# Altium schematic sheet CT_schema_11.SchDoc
size 297 x 239 mm
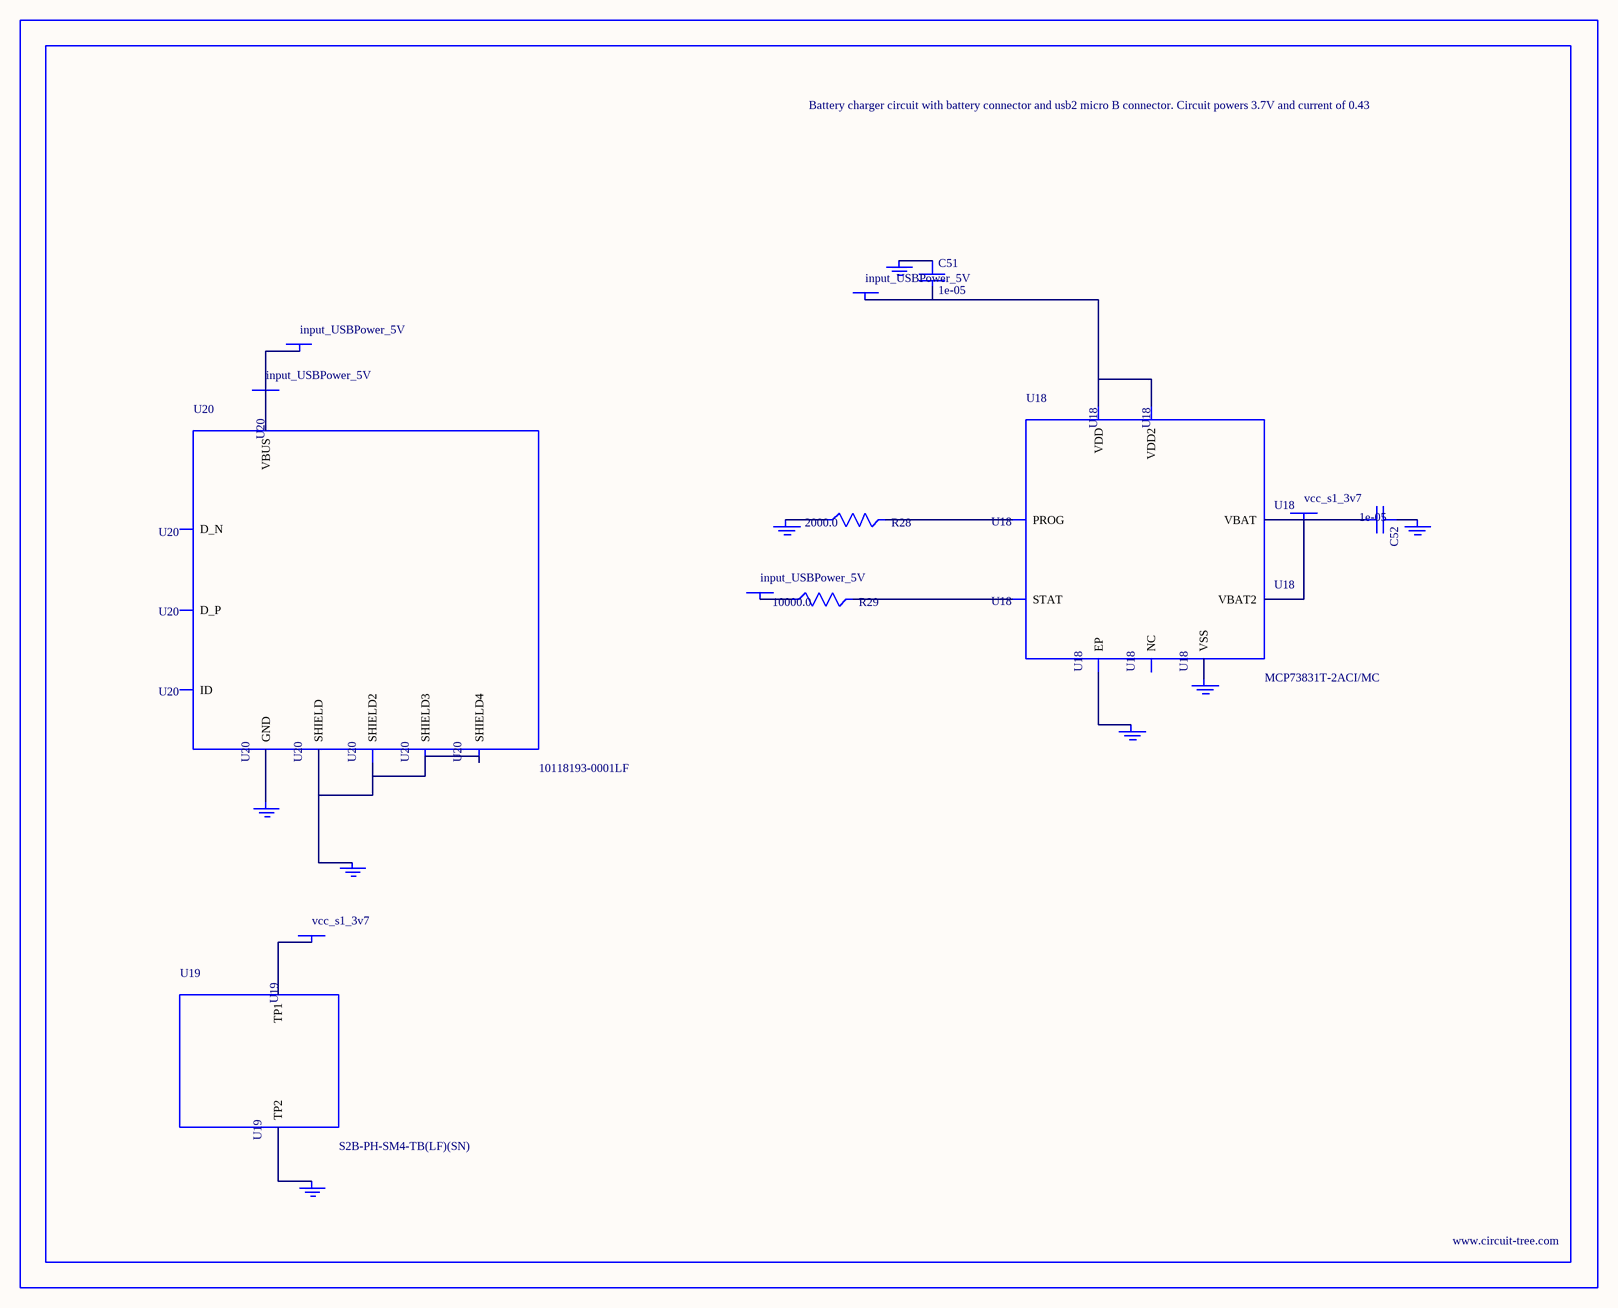
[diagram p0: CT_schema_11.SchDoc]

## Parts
BORDER10  (no value)
C51  1e-05  [C1206]
C52  1e-05  [C1206]
GND_INSTANCE_10_0  (no value)
GND_INSTANCE_10_1  (no value)
GND_INSTANCE_10_2  (no value)
GND_INSTANCE_10_3  (no value)
GND_INSTANCE_10_4  (no value)
GND_INSTANCE_10_5  (no value)
GND_INSTANCE_10_6  (no value)
GND_INSTANCE_10_7  (no value)
POWER_INSTANCE_10_0  input_USBPower_5V
POWER_INSTANCE_10_1  input_USBPower_5V
POWER_INSTANCE_10_2  vcc_s1_3v7
POWER_INSTANCE_10_3  vcc_s1_3v7
POWER_INSTANCE_10_4  input_USBPower_5V
POWER_INSTANCE_10_5  input_USBPower_5V
R28  2000.0  [R0603]
R29  10000.0  [R0603]
U18  MCP73831T-2ACI/MC  [DFN8_2X3MC]
U19  S2B-PH-SM4-TB(LF)(SN)  [JST-2-SMD]
U20  10118193-0001LF  [FCI_10118193-0001LF]

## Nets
NetC51_1: C51.1 GND_INSTANCE_10_0.0(GND)
NetC51_2: C51.2 POWER_INSTANCE_10_0.0(PWR) U18.1(VDD) U18.2(VDD2)
NetC52_1: C52.1 GND_INSTANCE_10_1.0(GND)
NetC52_2: C52.2 POWER_INSTANCE_10_2.0(PWR) U18.3(VBAT) U18.4(VBAT2)
NetGND_INSTANCE_10_2_0: GND_INSTANCE_10_2.0(GND) R28.1
NetGND_INSTANCE_10_3_0: GND_INSTANCE_10_3.0(GND) U18.9(EP)
NetGND_INSTANCE_10_4_0: GND_INSTANCE_10_4.0(GND) U18.6(VSS)
NetGND_INSTANCE_10_5_0: GND_INSTANCE_10_5.0(GND) U19.2(TP2)
NetGND_INSTANCE_10_6_0: GND_INSTANCE_10_6.0(GND) U20.6(SHIELD) U20.7(SHIELD2) U20.8(SHIELD3) U20.9(SHIELD4)
NetGND_INSTANCE_10_7_0: GND_INSTANCE_10_7.0(GND) U20.5(GND)
NetPOWER_INSTANCE_10_1_0: POWER_INSTANCE_10_1.0(PWR) R29.1
NetPOWER_INSTANCE_10_3_0: POWER_INSTANCE_10_3.0(PWR) U19.1(TP1)
NetPOWER_INSTANCE_10_4_0: POWER_INSTANCE_10_4.0(PWR) POWER_INSTANCE_10_5.0(PWR) U20.1(VBUS)
NetR28_2: R28.2 U18.8(PROG)
NetR29_2: R29.2 U18.5(STAT)

Not connected (* = marked no-connect by the designer): U18 7(NC); U20 2(D_N) 3(D_P) 4(ID)

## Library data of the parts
BORDER10 = BORDER_PAGE10
C51 C52 = C1206C106K3RACTU
GND_INSTANCE_10_0-GND_INSTANCE_10_7 = GND
POWER_INSTANCE_10_0-POWER_INSTANCE_10_5 = PWR
R28 = RC0603JR-072KL
R29 = RC0603JR-0710KL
